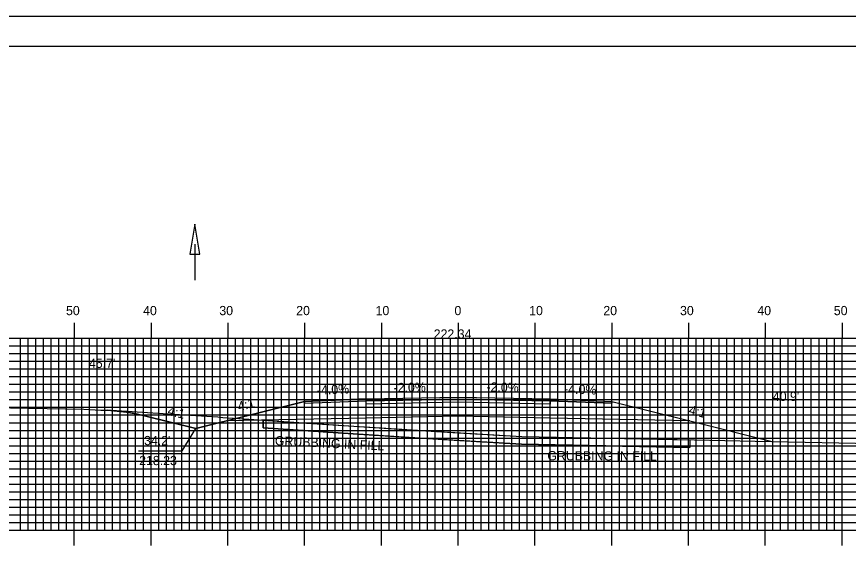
# Model space of a CAD drawing. Extents: x 1819637 to 1819981, y 442591 to 442811.
# Drawn here: x 1819745.7 to 1819854, y 442741.2 to 442810.5 of the extents above; entities that cross this region are included whole.
import ezdxf

# ---------------------------------------------------------------- set-up
doc = ezdxf.new("R2010")
doc.units = 0
for name, color, linetype in [('ANNOTATION', 7, 'Continuous'), ('BORDER', 7, 'Continuous'), ('D_Drainage_Ditch_Line', 7, 'Continuous'), ('D_Roadway_Centerline', 7, 'Continuous'), ('D_Roadway_Centerline_Text', 7, 'Continuous'), ('D_Roadway_Edge_Shoulder', 7, 'Continuous'), ('D_Roadway_Edge_TW', 7, 'Continuous'), ('D_Roadway_Pavement', 7, 'Continuous'), ('D_Roadway_SlopeLines', 7, 'Continuous'), ('D_Roadway_SubGrade', 7, 'Continuous'), ('D_Text_Standard', 7, 'Continuous'), ('GRUBBING IN FILL', 7, 'Continuous'), ('H_V ANNOTATION', 7, 'Continuous'), ('MAJOR', 7, 'Continuous'), ('MINOR', 7, 'Continuous'), ('PLOT BOUNDARY', 7, 'Continuous'), ('S_Roadway_Centerline', 7, 'Continuous')]:
    doc.layers.add(name, color=color, linetype=linetype)

msp = doc.modelspace()

# ---------------------------------------------------------------- linework, layer by layer
at = {"layer": 'ANNOTATION'}
msp.add_lwpolyline([(1819761.54, 442754.01), (1819767.24, 442754.01), (1819769, 442756.9)], dxfattribs=at)
at = {"layer": 'BORDER'}
msp.add_lwpolyline([(1819653.58, 442596.67), (1819973.58, 442596.67), (1819973.58, 442806.67), (1819653.58, 442806.67)], close=True, dxfattribs=at)
at = {"layer": 'D_Drainage_Ditch_Line'}
msp.add_line((1819768.88, 442780.91), (1819768.88, 442776.21), dxfattribs=at)
msp.add_lwpolyline([(1819768.22, 442779.6), (1819769.54, 442779.6), (1819768.88, 442783.54)], close=True, dxfattribs=at)
at = {"layer": 'D_Roadway_Centerline'}
msp.add_lwpolyline([(1819757.5, 442759.28), (1819758.75, 442759.18), (1819760, 442759.02), (1819761.25, 442758.8), (1819762.5, 442758.52), (1819769, 442756.9), (1819773, 442757.9), (1819783.18, 442760.44), (1819791.18, 442760.76), (1819803.18, 442761), (1819815.18, 442760.76), (1819823.18, 442760.44), (1819833.35, 442757.9), (1819844.1, 442755.21)], dxfattribs=at)
at = {"layer": 'D_Roadway_Edge_Shoulder'}
for points in [[(1819791.18, 442760.76), (1819783.18, 442760.44), (1819783.18, 442760.19), (1819791.18, 442760.51)], [(1819815.18, 442760.76), (1819823.18, 442760.44), (1819823.18, 442760.19), (1819815.18, 442760.51)]]:
    msp.add_lwpolyline(points, close=True, dxfattribs=at)
at = {"layer": 'D_Roadway_Edge_TW'}
msp.add_lwpolyline([(1819791.18, 442760.51), (1819791.18, 442760.76), (1819803.18, 442761), (1819815.18, 442760.76), (1819815.18, 442760.51), (1819803.18, 442760.75)], close=True, dxfattribs=at)
at = {"layer": 'D_Roadway_Pavement'}
msp.add_lwpolyline([(1819791.18, 442760.09), (1819791.18, 442760.51), (1819803.18, 442760.75), (1819815.18, 442760.51), (1819815.18, 442760.09), (1819803.18, 442760.33)], close=True, dxfattribs=at)
at = {"layer": 'D_Roadway_SlopeLines'}
for points in [[(1819783.18, 442760.44), (1819769, 442756.9)], [(1819823.18, 442760.44), (1819833.35, 442757.9), (1819844.1, 442755.21)], [(1819769, 442756.9), (1819762.5, 442758.52), (1819761.25, 442758.8), (1819760, 442759.02), (1819758.75, 442759.18), (1819757.5, 442759.28)]]:
    msp.add_lwpolyline(points, dxfattribs=at)
at = {"layer": 'D_Roadway_SubGrade'}
msp.add_lwpolyline([(1819791.18, 442758.26), (1819773, 442757.9), (1819783.18, 442760.44), (1819783.18, 442760.19), (1819791.18, 442760.51), (1819803.18, 442760.75), (1819815.18, 442760.51), (1819823.18, 442760.19), (1819823.18, 442760.44), (1819833.35, 442757.9), (1819815.18, 442758.26), (1819803.18, 442758.5)], close=True, dxfattribs=at)
at = {"layer": 'GRUBBING IN FILL'}
for p, q in [((1819777.79, 442757.99), (1819777.79, 442756.99)), ((1819777.79, 442757.99), (1819777.79, 442756.99)), ((1819833.35, 442755.45), (1819833.35, 442754.44)), ((1819833.35, 442755.45), (1819833.35, 442754.44))]:
    msp.add_line(p, q, dxfattribs=at)
for points in [[(1819777.79, 442757.99), (1819782.09, 442757.71), (1819789.59, 442757.21), (1819796.17, 442756.8), (1819803.18, 442756.36), (1819803.18, 442755.36), (1819796.1, 442755.8), (1819789.52, 442756.22), (1819783.66, 442756.6), (1819777.79, 442756.99)], [(1819777.79, 442757.99), (1819782.09, 442757.71), (1819789.59, 442757.21), (1819796.17, 442756.8), (1819803.18, 442756.36), (1819803.18, 442755.36), (1819796.1, 442755.8), (1819789.52, 442756.22), (1819783.66, 442756.6), (1819777.79, 442756.99)], [(1819803.18, 442756.36), (1819811.49, 442755.85), (1819822.72, 442755.64), (1819833.35, 442755.45), (1819833.35, 442754.44), (1819822.4, 442754.65), (1819811.45, 442754.86), (1819803.18, 442755.36)], [(1819803.18, 442756.36), (1819811.49, 442755.85), (1819822.72, 442755.64), (1819833.35, 442755.45), (1819833.35, 442754.44), (1819822.4, 442754.65), (1819811.45, 442754.86), (1819803.18, 442755.36)]]:
    msp.add_lwpolyline(points, close=True, dxfattribs=at)
msp.add_lwpolyline([(1819777.79, 442756.99), (1819789.52, 442756.22), (1819802.68, 442755.39), (1819811.45, 442754.86), (1819833.35, 442754.44)], dxfattribs=at)
msp.add_lwpolyline([(1819777.79, 442756.99), (1819789.52, 442756.22), (1819802.68, 442755.39), (1819811.45, 442754.86), (1819833.35, 442754.44)], dxfattribs=at)
at = {"layer": 'MAJOR'}
for p, q in [((1819753.18, 442770.67), (1819753.18, 442768.67)), ((1819763.18, 442770.67), (1819763.18, 442768.67)), ((1819773.18, 442770.67), (1819773.18, 442768.67)), ((1819783.18, 442770.67), (1819783.18, 442768.67)), ((1819793.18, 442770.67), (1819793.18, 442768.67)), ((1819803.18, 442770.67), (1819803.18, 442768.67)), ((1819813.18, 442770.67), (1819813.18, 442768.67)), ((1819823.18, 442770.67), (1819823.18, 442768.67)), ((1819833.18, 442770.67), (1819833.18, 442768.67)), ((1819843.18, 442770.67), (1819843.18, 442768.67)), ((1819853.18, 442770.67), (1819853.18, 442768.67)), ((1819663.18, 442768.67), (1819943.18, 442768.67)), ((1819663.18, 442768.67), (1819943.18, 442768.67)), ((1819753.18, 442743.67), (1819753.18, 442768.67)), ((1819763.18, 442743.67), (1819763.18, 442768.67)), ((1819773.18, 442743.67), (1819773.18, 442768.67)), ((1819783.18, 442743.67), (1819783.18, 442768.67)), ((1819793.18, 442743.67), (1819793.18, 442768.67)), ((1819803.18, 442743.67), (1819803.18, 442768.67)), ((1819813.18, 442743.67), (1819813.18, 442768.67)), ((1819823.18, 442743.67), (1819823.18, 442768.67)), ((1819833.18, 442743.67), (1819833.18, 442768.67)), ((1819843.18, 442743.67), (1819843.18, 442768.67)), ((1819853.18, 442743.67), (1819853.18, 442768.67)), ((1819663.18, 442763.67), (1819943.18, 442763.67)), ((1819663.18, 442758.67), (1819943.18, 442758.67)), ((1819663.18, 442753.67), (1819943.18, 442753.67)), ((1819663.18, 442748.67), (1819943.18, 442748.67)), ((1819663.18, 442743.67), (1819943.18, 442743.67)), ((1819663.18, 442743.67), (1819943.18, 442743.67)), ((1819753.18, 442741.66), (1819753.18, 442743.67)), ((1819763.18, 442741.66), (1819763.18, 442743.67)), ((1819773.18, 442741.66), (1819773.18, 442743.67)), ((1819783.18, 442741.66), (1819783.18, 442743.67)), ((1819793.18, 442741.66), (1819793.18, 442743.67)), ((1819803.18, 442741.66), (1819803.18, 442743.67)), ((1819813.18, 442741.66), (1819813.18, 442743.67)), ((1819823.18, 442741.66), (1819823.18, 442743.67)), ((1819833.18, 442741.66), (1819833.18, 442743.67)), ((1819843.18, 442741.66), (1819843.18, 442743.67)), ((1819853.18, 442741.66), (1819853.18, 442743.67))]:
    msp.add_line(p, q, dxfattribs=at)
at = {"layer": 'MINOR'}
for p, q in [((1819746.18, 442743.67), (1819746.18, 442768.67)), ((1819747.18, 442743.67), (1819747.18, 442768.67)), ((1819748.18, 442743.67), (1819748.18, 442768.67)), ((1819749.18, 442743.67), (1819749.18, 442768.67)), ((1819750.18, 442743.67), (1819750.18, 442768.67)), ((1819751.18, 442743.67), (1819751.18, 442768.67)), ((1819752.18, 442743.67), (1819752.18, 442768.67)), ((1819754.18, 442743.67), (1819754.18, 442768.67)), ((1819755.18, 442743.67), (1819755.18, 442768.67)), ((1819756.18, 442743.67), (1819756.18, 442768.67)), ((1819757.18, 442743.67), (1819757.18, 442768.67)), ((1819758.18, 442743.67), (1819758.18, 442768.67)), ((1819759.18, 442743.67), (1819759.18, 442768.67)), ((1819760.18, 442743.67), (1819760.18, 442768.67)), ((1819761.18, 442743.67), (1819761.18, 442768.67)), ((1819762.18, 442743.67), (1819762.18, 442768.67)), ((1819764.18, 442743.67), (1819764.18, 442768.67)), ((1819765.18, 442743.67), (1819765.18, 442768.67)), ((1819766.18, 442743.67), (1819766.18, 442768.67)), ((1819767.18, 442743.67), (1819767.18, 442768.67)), ((1819768.18, 442743.67), (1819768.18, 442768.67)), ((1819769.18, 442743.67), (1819769.18, 442768.67)), ((1819770.18, 442743.67), (1819770.18, 442768.67)), ((1819771.18, 442743.67), (1819771.18, 442768.67)), ((1819772.18, 442743.67), (1819772.18, 442768.67)), ((1819774.18, 442743.67), (1819774.18, 442768.67)), ((1819775.18, 442743.67), (1819775.18, 442768.67)), ((1819776.18, 442743.67), (1819776.18, 442768.67)), ((1819777.18, 442743.67), (1819777.18, 442768.67)), ((1819778.18, 442743.67), (1819778.18, 442768.67)), ((1819779.18, 442743.67), (1819779.18, 442768.67)), ((1819780.18, 442743.67), (1819780.18, 442768.67)), ((1819781.18, 442743.67), (1819781.18, 442768.67)), ((1819782.18, 442743.67), (1819782.18, 442768.67)), ((1819784.18, 442743.67), (1819784.18, 442768.67)), ((1819785.18, 442743.67), (1819785.18, 442768.67)), ((1819786.18, 442743.67), (1819786.18, 442768.67)), ((1819787.18, 442743.67), (1819787.18, 442768.67)), ((1819788.18, 442743.67), (1819788.18, 442768.67)), ((1819789.18, 442743.67), (1819789.18, 442768.67)), ((1819790.18, 442743.67), (1819790.18, 442768.67)), ((1819791.18, 442743.67), (1819791.18, 442768.67)), ((1819792.18, 442743.67), (1819792.18, 442768.67)), ((1819794.18, 442743.67), (1819794.18, 442768.67)), ((1819795.18, 442743.67), (1819795.18, 442768.67)), ((1819796.18, 442743.67), (1819796.18, 442768.67)), ((1819797.18, 442743.67), (1819797.18, 442768.67)), ((1819798.18, 442743.67), (1819798.18, 442768.67)), ((1819799.18, 442743.67), (1819799.18, 442768.67)), ((1819800.18, 442743.67), (1819800.18, 442768.67)), ((1819801.18, 442743.67), (1819801.18, 442768.67)), ((1819802.18, 442743.67), (1819802.18, 442768.67)), ((1819804.18, 442743.67), (1819804.18, 442768.67)), ((1819805.18, 442743.67), (1819805.18, 442768.67)), ((1819806.18, 442743.67), (1819806.18, 442768.67)), ((1819807.18, 442743.67), (1819807.18, 442768.67)), ((1819808.18, 442743.67), (1819808.18, 442768.67)), ((1819809.18, 442743.67), (1819809.18, 442768.67)), ((1819810.18, 442743.67), (1819810.18, 442768.67)), ((1819811.18, 442743.67), (1819811.18, 442768.67)), ((1819812.18, 442743.67), (1819812.18, 442768.67)), ((1819814.18, 442743.67), (1819814.18, 442768.67)), ((1819815.18, 442743.67), (1819815.18, 442768.67)), ((1819816.18, 442743.67), (1819816.18, 442768.67)), ((1819817.18, 442743.67), (1819817.18, 442768.67)), ((1819818.18, 442743.67), (1819818.18, 442768.67)), ((1819819.18, 442743.67), (1819819.18, 442768.67)), ((1819820.18, 442743.67), (1819820.18, 442768.67)), ((1819821.18, 442743.67), (1819821.18, 442768.67)), ((1819822.18, 442743.67), (1819822.18, 442768.67)), ((1819824.18, 442743.67), (1819824.18, 442768.67)), ((1819825.18, 442743.67), (1819825.18, 442768.67)), ((1819826.18, 442743.67), (1819826.18, 442768.67)), ((1819827.18, 442743.67), (1819827.18, 442768.67)), ((1819828.18, 442743.67), (1819828.18, 442768.67)), ((1819829.18, 442743.67), (1819829.18, 442768.67)), ((1819830.18, 442743.67), (1819830.18, 442768.67)), ((1819831.18, 442743.67), (1819831.18, 442768.67)), ((1819832.18, 442743.67), (1819832.18, 442768.67)), ((1819834.18, 442743.67), (1819834.18, 442768.67)), ((1819835.18, 442743.67), (1819835.18, 442768.67)), ((1819836.18, 442743.67), (1819836.18, 442768.67)), ((1819837.18, 442743.67), (1819837.18, 442768.67)), ((1819838.18, 442743.67), (1819838.18, 442768.67)), ((1819839.18, 442743.67), (1819839.18, 442768.67)), ((1819840.18, 442743.67), (1819840.18, 442768.67)), ((1819841.18, 442743.67), (1819841.18, 442768.67)), ((1819842.18, 442743.67), (1819842.18, 442768.67)), ((1819844.18, 442743.67), (1819844.18, 442768.67)), ((1819845.18, 442743.67), (1819845.18, 442768.67)), ((1819846.18, 442743.67), (1819846.18, 442768.67)), ((1819847.18, 442743.67), (1819847.18, 442768.67)), ((1819848.18, 442743.67), (1819848.18, 442768.67)), ((1819849.18, 442743.67), (1819849.18, 442768.67)), ((1819850.18, 442743.67), (1819850.18, 442768.67)), ((1819851.18, 442743.67), (1819851.18, 442768.67)), ((1819852.18, 442743.67), (1819852.18, 442768.67)), ((1819663.18, 442767.67), (1819943.18, 442767.67)), ((1819663.18, 442766.67), (1819943.18, 442766.67)), ((1819663.18, 442765.67), (1819943.18, 442765.67)), ((1819663.18, 442764.67), (1819943.18, 442764.67)), ((1819663.18, 442762.67), (1819943.18, 442762.67)), ((1819663.18, 442761.67), (1819943.18, 442761.67)), ((1819663.18, 442760.67), (1819943.18, 442760.67)), ((1819663.18, 442759.67), (1819943.18, 442759.67)), ((1819663.18, 442757.67), (1819943.18, 442757.67)), ((1819663.18, 442756.67), (1819943.18, 442756.67)), ((1819663.18, 442755.67), (1819943.18, 442755.67)), ((1819663.18, 442754.67), (1819943.18, 442754.67)), ((1819663.18, 442752.67), (1819943.18, 442752.67)), ((1819663.18, 442751.67), (1819943.18, 442751.67)), ((1819663.18, 442750.67), (1819943.18, 442750.67)), ((1819663.18, 442749.67), (1819943.18, 442749.67)), ((1819663.18, 442747.67), (1819943.18, 442747.67)), ((1819663.18, 442746.67), (1819943.18, 442746.67)), ((1819663.18, 442745.67), (1819943.18, 442745.67)), ((1819663.18, 442744.67), (1819943.18, 442744.67))]:
    msp.add_line(p, q, dxfattribs=at)
at = {"layer": 'PLOT BOUNDARY'}
msp.add_lwpolyline([(1819637.39, 442590.55), (1819977.39, 442590.55), (1819977.39, 442810.55), (1819637.39, 442810.55)], close=True, dxfattribs=at)
at = {"layer": 'S_Roadway_Centerline'}
msp.add_lwpolyline([(1819663.18, 442761.42), (1819664.51, 442761.32), (1819685.77, 442760.93), (1819690.3, 442760.87), (1819692.65, 442760.78), (1819712.98, 442760.35), (1819723.25, 442760.08), (1819731.45, 442760.07), (1819740.05, 442759.71), (1819754.45, 442759.43), (1819756.64, 442759.29), (1819757.97, 442759.28), (1819765.44, 442758.81), (1819771.89, 442758.41), (1819772.54, 442758.34), (1819774.6, 442758.21), (1819789.59, 442757.21), (1819802.74, 442756.39), (1819811.49, 442755.85), (1819833.95, 442755.43), (1819841.85, 442755.26), (1819859.26, 442754.92)], dxfattribs=at)

# ---------------------------------------------------------------- texts
at = {"layer": 'ANNOTATION'}
for s, rotation, p in [('-4.0%', 2.2906, (1819784.81, 442761.31)), ('-2.0%', 1.1458, (1819794.78, 442761.63)), ('-2.0%', 358.8542, (1819806.86, 442761.73)), ('-4.0%', 357.7094, (1819816.97, 442761.49)), ('4:1', 14.0362, (1819774.63, 442759.17)), ('4:1', 345.9638, (1819765.26, 442758.7)), ('4:1', 345.9638, (1819833.14, 442758.81))]:
    msp.add_text(s, height=1.2, rotation=rotation, dxfattribs=at).set_placement(p)
for s, p in [("34.2'", (1819762.28, 442754.74)), ('218.23', (1819761.64, 442752.14))]:
    msp.add_text(s, height=1.2, dxfattribs=at).set_placement(p)
at = {"layer": 'D_Roadway_Centerline'}
for s, p in [('C', (1819803.17, 442761)), ('L', (1819803.18, 442760.99))]:
    msp.add_text(s, height=0.0146, dxfattribs=at).set_placement(p)
at = {"layer": 'D_Roadway_Centerline_Text'}
msp.add_text('222.34', height=1.2, dxfattribs=at).set_placement((1819800, 442768.62))
at = {"layer": 'D_Text_Standard'}
for s, p in [("45.7'", (1819755.1, 442764.8)), ("40.9'", (1819844.17, 442760.49))]:
    msp.add_text(s, height=1.2, dxfattribs=at).set_placement(p)
at = {"layer": 'GRUBBING IN FILL'}
for rotation, p in [(357.22, (1819779.29, 442754.74)), (359.8053, (1819814.8, 442752.77))]:
    msp.add_text('GRUBBING IN FILL', height=1.2, rotation=rotation, dxfattribs=at).set_placement(p)
at = {"layer": 'H_V ANNOTATION'}
for s, p in [('50', (1819752.11, 442771.67)), ('40', (1819762.15, 442771.67)), ('30', (1819772.08, 442771.67)), ('20', (1819782.09, 442771.67)), ('10', (1819792.43, 442771.67)), ('0', (1819802.7, 442771.67)), ('10', (1819812.43, 442771.67)), ('20', (1819822.09, 442771.67)), ('30', (1819832.08, 442771.67)), ('40', (1819842.15, 442771.67)), ('50', (1819852.11, 442771.67))]:
    msp.add_text(s, height=1.2, dxfattribs=at).set_placement(p)

doc.saveas('drawing.dxf')
